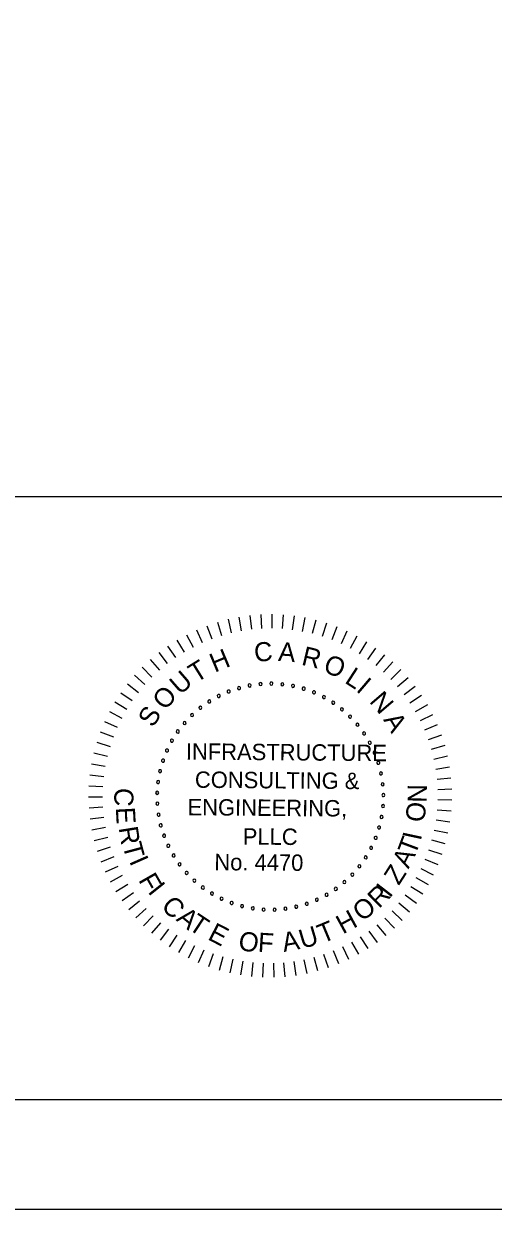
# Model space of a CAD drawing. Extents: x 1970675.2 to 1970711.3, y 796145.2 to 796167.2.
# Drawn here: x 1970700.45 to 1970702.59, y 796145.25 to 796150.65 of the extents above; entities that cross this region are included whole.
import ezdxf

# ---------------------------------------------------------------- set-up
doc = ezdxf.new("R2010")
doc.units = 0
for name, color, linetype in [('BR_BORDER LINES', 7, 'Continuous'), ('BR_TEXT', 7, 'Continuous'), ('Level 31', 7, 'Continuous')]:
    doc.layers.add(name, color=color, linetype=linetype)

msp = doc.modelspace()

# ---------------------------------------------------------------- linework, layer by layer
at = {"layer": 'BR_BORDER LINES'}
for p, q in [((1970697.8703, 796148.4964), (1970703.2355, 796148.4964)), ((1970677.0698, 796145.7463), (1970710.7358, 796145.7463))]:
    msp.add_line(p, q, dxfattribs=at)
at = {"layer": 'BR_TEXT'}
for p, q in [((1970701.4761, 796147.9545), (1970701.4834, 796147.8913)), ((1970701.5265, 796147.9587), (1970701.5298, 796147.8951)), ((1970701.5769, 796147.9597), (1970701.5764, 796147.8961)), ((1970701.6274, 796147.9577), (1970701.623, 796147.8942)), ((1970701.2802, 796147.9077), (1970701.3025, 796147.8481)), ((1970701.328, 796147.9239), (1970701.3466, 796147.863)), ((1970701.3767, 796147.9371), (1970701.3916, 796147.8752)), ((1970701.4262, 796147.9473), (1970701.4372, 796147.8846)), ((1970701.6776, 796147.9526), (1970701.6693, 796147.8895)), ((1970701.7274, 796147.9445), (1970701.7153, 796147.882)), ((1970701.7767, 796147.9333), (1970701.7608, 796147.8717)), ((1970701.8251, 796147.9192), (1970701.8055, 796147.8586)), ((1970701.8726, 796147.9021), (1970701.8494, 796147.8428)), ((1970701.1879, 796147.8668), (1970701.2173, 796147.8103)), ((1970701.2334, 796147.8887), (1970701.2593, 796147.8305)), ((1970701.919, 796147.8822), (1970701.8922, 796147.8244)), ((1970701.9641, 796147.8594), (1970701.9338, 796147.8034)), ((1970701.1014, 796147.8149), (1970701.1374, 796147.7625)), ((1970701.1439, 796147.8422), (1970701.1766, 796147.7876)), ((1970702.0077, 796147.834), (1970701.974, 796147.78)), ((1970702.0497, 796147.8059), (1970702.0128, 796147.7541)), ((1970701.0217, 796147.7529), (1970701.0639, 796147.7052)), ((1970701.0606, 796147.7852), (1970701.0998, 796147.735)), ((1970702.0899, 796147.7754), (1970702.0499, 796147.7259)), ((1970702.1281, 796147.7424), (1970702.0852, 796147.6954)), ((1970700.9849, 796147.7184), (1970701.0299, 796147.6734)), ((1970702.1643, 796147.7072), (1970702.1186, 796147.6629)), ((1970700.9179, 796147.643), (1970700.968, 796147.6037)), ((1970700.9502, 796147.6817), (1970700.9979, 796147.6395)), ((1970702.1982, 796147.6699), (1970702.1499, 796147.6284)), ((1970702.2299, 796147.6305), (1970702.1791, 796147.5921)), ((1970700.8879, 796147.6023), (1970700.9404, 796147.5662)), ((1970702.259, 796147.5893), (1970702.206, 796147.5541)), ((1970700.8605, 796147.5599), (1970700.9151, 796147.5271)), ((1970702.2856, 796147.5464), (1970702.2305, 796147.5145)), ((1970700.8137, 796147.4705), (1970700.8719, 796147.4445)), ((1970700.8358, 796147.5159), (1970700.8922, 796147.4865)), ((1970702.3095, 796147.5019), (1970702.2526, 796147.4734)), ((1970700.7945, 796147.4238), (1970700.8541, 796147.4014)), ((1970702.3307, 796147.4561), (1970702.2722, 796147.4311)), ((1970700.7782, 796147.3761), (1970700.839, 796147.3574)), ((1970702.3491, 796147.4091), (1970702.2891, 796147.3877)), ((1970702.3645, 796147.361), (1970702.3033, 796147.3433)), ((1970700.7648, 796147.3274), (1970700.8267, 796147.3124)), ((1970702.377, 796147.3121), (1970702.3148, 796147.2982)), ((1970700.7543, 796147.278), (1970700.817, 796147.2668)), ((1970702.3864, 796147.2625), (1970702.3236, 796147.2524)), ((1970700.747, 796147.228), (1970700.8102, 796147.2207)), ((1970702.3929, 796147.2124), (1970702.3295, 796147.2062)), ((1970700.7426, 796147.1777), (1970700.8062, 796147.1743)), ((1970702.3963, 796147.1621), (1970702.3326, 796147.1597)), ((1970700.7414, 796147.1273), (1970700.8051, 796147.1277)), ((1970702.3965, 796147.1116), (1970702.3329, 796147.1131)), ((1970700.7432, 796147.0768), (1970700.8067, 796147.0812)), ((1970702.3938, 796147.0612), (1970702.3303, 796147.0666)), ((1970700.7481, 796147.0266), (1970700.8113, 796147.0348)), ((1970700.7561, 796146.9767), (1970700.8186, 796146.9888)), ((1970702.3879, 796147.011), (1970702.3249, 796147.0203)), ((1970700.7671, 796146.9275), (1970700.8287, 796146.9433)), ((1970702.3671, 796146.9123), (1970702.3057, 796146.9291)), ((1970702.379, 796146.9613), (1970702.3167, 796146.9744)), ((1970700.781, 796146.8789), (1970700.8416, 796146.8985)), ((1970702.3522, 796146.864), (1970702.2919, 796146.8846)), ((1970700.7979, 796146.8314), (1970700.8572, 796146.8546)), ((1970702.3344, 796146.8168), (1970702.2755, 796146.841)), ((1970700.8177, 796146.7849), (1970700.8755, 796146.8117)), ((1970700.8403, 796146.7397), (1970700.8963, 796146.77)), ((1970702.3138, 796146.7707), (1970702.2564, 796146.7985)), ((1970700.8655, 796146.696), (1970700.9196, 796146.7297)), ((1970702.2643, 796146.6828), (1970702.2107, 796146.7173)), ((1970702.2904, 796146.726), (1970702.2348, 796146.7572)), ((1970700.8934, 796146.654), (1970700.9453, 796146.6908)), ((1970702.2356, 796146.6412), (1970702.1843, 796146.6789)), ((1970700.9238, 796146.6137), (1970700.9734, 796146.6536)), ((1970700.9566, 796146.5753), (1970701.0037, 796146.6182)), ((1970702.1709, 796146.5638), (1970702.1245, 796146.6074)), ((1970702.2044, 796146.6015), (1970702.1555, 796146.6423)), ((1970700.9917, 796146.539), (1970701.0361, 796146.5847)), ((1970701.0289, 796146.5049), (1970701.0704, 796146.5532)), ((1970702.1351, 796146.5281), (1970702.0915, 796146.5745)), ((1970701.0682, 796146.4731), (1970701.1066, 796146.5239)), ((1970701.1093, 796146.4438), (1970701.1446, 796146.4968)), ((1970702.0574, 796146.4637), (1970702.0198, 796146.5151)), ((1970702.0973, 796146.4948), (1970702.0566, 796146.5437)), ((1970701.1521, 796146.4171), (1970701.1841, 796146.4721)), ((1970701.1965, 796146.393), (1970701.225, 796146.4499)), ((1970701.9276, 796146.386), (1970701.9, 796146.4434)), ((1970701.9725, 796146.4093), (1970701.9414, 796146.4648)), ((1970702.0158, 796146.4352), (1970701.9813, 796146.4888)), ((1970701.2422, 796146.3716), (1970701.2673, 796146.4302)), ((1970701.2892, 796146.3531), (1970701.3106, 796146.4131)), ((1970701.3372, 796146.3375), (1970701.3549, 796146.3986)), ((1970701.386, 796146.3248), (1970701.4001, 796146.3869)), ((1970701.7859, 796146.3332), (1970701.7691, 796146.3947)), ((1970701.8342, 796146.3479), (1970701.8137, 796146.4082)), ((1970701.8815, 796146.3656), (1970701.8574, 796146.4245)), ((1970701.4356, 796146.3152), (1970701.4458, 796146.378)), ((1970701.4856, 796146.3086), (1970701.492, 796146.3719)), ((1970701.536, 796146.305), (1970701.5385, 796146.3686)), ((1970701.5865, 796146.3045), (1970701.5851, 796146.3682)), ((1970701.6369, 796146.3071), (1970701.6316, 796146.3706)), ((1970701.6871, 796146.3128), (1970701.6779, 796146.3758)), ((1970701.7368, 796146.3215), (1970701.7238, 796146.3838))]:
    msp.add_line(p, q, dxfattribs=at)
for centre, start, end in [((1970701.4268, 796147.6235), 16.1422, 196.1422), ((1970701.4753, 796147.635), 10.6038, 190.6038), ((1970701.4753, 796147.635), 190.6038, 10.6038), ((1970701.5247, 796147.6417), 5.0653, 185.0653), ((1970701.5247, 796147.6417), 185.0653, 5.0653), ((1970701.5745, 796147.6436), 359.5268, 179.5268), ((1970701.5745, 796147.6436), 179.5268, 359.5268), ((1970701.6242, 796147.6407), 173.9884, 353.9884), ((1970701.6242, 796147.6407), 353.9884, 173.9884), ((1970701.6735, 796147.6329), 168.4499, 348.4499), ((1970701.6735, 796147.6329), 348.4499, 168.4499), ((1970701.3343, 796147.587), 27.2191, 207.2191), ((1970701.3343, 796147.587), 207.2191, 27.2191), ((1970701.3797, 796147.6075), 21.6807, 201.6807), ((1970701.3797, 796147.6075), 201.6807, 21.6807), ((1970701.4268, 796147.6235), 196.1422, 16.1422), ((1970701.7217, 796147.6205), 162.9114, 342.9114), ((1970701.7217, 796147.6205), 342.9114, 162.9114), ((1970701.7686, 796147.6035), 157.373, 337.373), ((1970701.7686, 796147.6035), 337.373, 157.373), ((1970701.8135, 796147.582), 151.8345, 331.8345), ((1970701.8135, 796147.582), 331.8345, 151.8345), ((1970701.2504, 796147.5333), 38.2961, 218.2961), ((1970701.2504, 796147.5333), 218.2961, 38.2961), ((1970701.291, 796147.5621), 32.7576, 212.7576), ((1970701.291, 796147.5621), 212.7576, 32.7576), ((1970701.8562, 796147.5563), 146.2961, 326.2961), ((1970701.8562, 796147.5563), 326.2961, 146.2961), ((1970701.8962, 796147.5266), 140.7576, 320.7576), ((1970701.8962, 796147.5266), 320.7576, 140.7576), ((1970701.1785, 796147.4645), 49.373, 229.373), ((1970701.1785, 796147.4645), 229.373, 49.373), ((1970701.2128, 796147.5006), 43.8345, 223.8345), ((1970701.2128, 796147.5006), 223.8345, 43.8345), ((1970701.9332, 796147.4932), 135.2191, 315.2191), ((1970701.9332, 796147.4932), 315.2191, 135.2191), ((1970701.1478, 796147.4252), 54.9114, 234.9114), ((1970701.1478, 796147.4252), 234.9114, 54.9114), ((1970701.9668, 796147.4564), 129.6807, 309.6807), ((1970701.9668, 796147.4564), 309.6807, 129.6807), ((1970701.9966, 796147.4165), 124.1422, 304.1422), ((1970701.9966, 796147.4165), 304.1422, 124.1422), ((1970701.1211, 796147.3831), 60.4499, 240.4499), ((1970701.1211, 796147.3831), 240.4499, 60.4499), ((1970702.0225, 796147.3739), 118.6038, 298.6038), ((1970702.0225, 796147.3739), 298.6038, 118.6038), ((1970701.0986, 796147.3387), 65.9884, 245.9884), ((1970701.0986, 796147.3387), 245.9884, 65.9884), ((1970702.0441, 796147.329), 113.0653, 293.0653), ((1970702.0441, 796147.329), 293.0653, 113.0653), ((1970701.0804, 796147.2923), 71.5268, 251.5268), ((1970701.0804, 796147.2923), 251.5268, 71.5268), ((1970702.0613, 796147.2822), 107.5268, 287.5268), ((1970702.0613, 796147.2822), 287.5268, 107.5268), ((1970701.0579, 796147.1953), 82.6038, 262.6038), ((1970701.0579, 796147.1953), 262.6038, 82.6038), ((1970701.0668, 796147.2443), 77.0653, 257.0653), ((1970701.0668, 796147.2443), 257.0653, 77.0653), ((1970702.0739, 796147.234), 101.9884, 281.9884), ((1970702.0739, 796147.234), 281.9884, 101.9884), ((1970701.0538, 796147.1456), 88.1422, 268.1422), ((1970701.0538, 796147.1456), 268.1422, 88.1422), ((1970702.0818, 796147.1848), 96.4499, 276.4499), ((1970702.0818, 796147.1848), 276.4499, 96.4499), ((1970701.0545, 796147.0958), 93.6807, 273.6807), ((1970701.0545, 796147.0958), 273.6807, 93.6807), ((1970702.0832, 796147.0853), 85.373, 265.373), ((1970702.0849, 796147.1351), 90.9114, 270.9114), ((1970702.0832, 796147.0853), 265.373, 85.373), ((1970702.0849, 796147.1351), 270.9114, 90.9114), ((1970701.06, 796147.0463), 99.2191, 279.2191), ((1970701.06, 796147.0463), 279.2191, 99.2191), ((1970702.0766, 796147.0359), 79.8345, 259.8345), ((1970702.0766, 796147.0359), 259.8345, 79.8345), ((1970701.0703, 796146.9975), 104.7576, 284.7576), ((1970701.0703, 796146.9975), 284.7576, 104.7576), ((1970702.0654, 796146.9873), 74.2961, 254.2961), ((1970702.0654, 796146.9873), 254.2961, 74.2961), ((1970701.0852, 796146.95), 110.2961, 290.2961), ((1970701.0852, 796146.95), 290.2961, 110.2961), ((1970702.0495, 796146.9401), 68.7576, 248.7576), ((1970702.0495, 796146.9401), 248.7576, 68.7576), ((1970701.1046, 796146.9041), 115.8345, 295.8345), ((1970701.1046, 796146.9041), 295.8345, 115.8345), ((1970702.0291, 796146.8946), 63.2191, 243.2191), ((1970702.0291, 796146.8946), 243.2191, 63.2191), ((1970701.1284, 796146.8603), 121.373, 301.373), ((1970701.1284, 796146.8603), 301.373, 121.373), ((1970701.1563, 796146.819), 126.9114, 306.9114), ((1970701.1563, 796146.819), 306.9114, 126.9114), ((1970702.0045, 796146.8513), 57.6807, 237.6807), ((1970702.0045, 796146.8513), 237.6807, 57.6807), ((1970701.188, 796146.7806), 132.4499, 312.4499), ((1970701.188, 796146.7806), 312.4499, 132.4499), ((1970701.9432, 796146.7728), 46.6038, 226.6038), ((1970701.9432, 796146.7728), 226.6038, 46.6038), ((1970701.9758, 796146.8106), 52.1422, 232.1422), ((1970701.9758, 796146.8106), 232.1422, 52.1422), ((1970701.2233, 796146.7454), 137.9884, 317.9884), ((1970701.2233, 796146.7454), 317.9884, 137.9884), ((1970701.2618, 796146.7138), 143.5268, 323.5268), ((1970701.2618, 796146.7138), 323.5268, 143.5268), ((1970701.8681, 796146.7076), 35.5268, 215.5268), ((1970701.8681, 796146.7076), 215.5268, 35.5268), ((1970701.9072, 796146.7384), 41.0653, 221.0653), ((1970701.9072, 796146.7384), 221.0653, 41.0653), ((1970701.3032, 796146.6861), 149.0653, 329.0653), ((1970701.3032, 796146.6861), 329.0653, 149.0653), ((1970701.3471, 796146.6625), 154.6038, 334.6038), ((1970701.3471, 796146.6625), 334.6038, 154.6038), ((1970701.7817, 796146.658), 24.4499, 204.4499), ((1970701.7817, 796146.658), 204.4499, 24.4499), ((1970701.8261, 796146.6807), 29.9884, 209.9884), ((1970701.8261, 796146.6807), 209.9884, 29.9884), ((1970701.3931, 796146.6432), 160.1422, 340.1422), ((1970701.3931, 796146.6432), 340.1422, 160.1422), ((1970701.4407, 796146.6285), 165.6807, 345.6807), ((1970701.4407, 796146.6285), 345.6807, 165.6807), ((1970701.4895, 796146.6184), 171.2191, 351.2191), ((1970701.4895, 796146.6184), 351.2191, 171.2191), ((1970701.539, 796146.6131), 356.7576, 176.7576), ((1970701.539, 796146.6131), 176.7576, 356.7576), ((1970701.5889, 796146.6126), 2.2961, 182.2961), ((1970701.5889, 796146.6126), 182.2961, 2.2961), ((1970701.6385, 796146.6169), 7.8345, 187.8345), ((1970701.6385, 796146.6169), 187.8345, 7.8345), ((1970701.6875, 796146.6259), 13.373, 193.373), ((1970701.6875, 796146.6259), 193.373, 13.373), ((1970701.7354, 796146.6397), 18.9114, 198.9114), ((1970701.7354, 796146.6397), 198.9114, 18.9114)]:
    msp.add_arc(centre, 0.00701, start, end, dxfattribs=at)
at = {"layer": 'Level 31'}
msp.add_lwpolyline([(1970675.2365, 796145.2464), (1970711.2364, 796145.2464), (1970711.2364, 796167.2463), (1970675.2365, 796167.2463)], close=True, dxfattribs=at)

# ---------------------------------------------------------------- texts
at = {"layer": 'BR_TEXT'}
for s, height, rotation, p in [('H', 0.0872, 22.7882, (1970701.3162, 796147.6927)), ('C', 0.0872, 4.7281, (1970701.499, 796147.7421)), ('A', 0.0872, 355.6981, (1970701.6035, 796147.7471)), ('R', 0.0872, 346.6681, (1970701.7077, 796147.7301)), ('T', 0.0872, 31.8182, (1970701.2313, 796147.6451)), ('O', 0.0872, 337.638, (1970701.8055, 796147.7003)), ('U', 0.0872, 40.8482, (1970701.158, 796147.589)), ('L', 0.0872, 327.108, (1970701.9043, 796147.6498)), ('I', 0.0872, 319.578, (1970701.9569, 796147.612)), ('O', 0.0872, 49.8782, (1970701.091, 796147.518)), ('N', 0.0872, 310.548, (1970702.0177, 796147.5612)), ('S', 0.0872, 58.9083, (1970701.0356, 796147.4398)), ('A', 0.0872, 301.5179, (1970702.0828, 796147.4788)), ('INFRASTRUCTURE', 0.074771, 359.5268, (1970701.1842, 796147.2972)), ('CONSULTING &', 0.074771, 359.5268, (1970701.2255, 796147.1686)), ('C', 0.0872, 267.025, (1970700.8606, 796147.1698)), ('N', 0.0872, 89.2085, (1970702.2821, 796147.1001)), ('ENGINEERING,', 0.074771, 359.5268, (1970701.1919, 796147.0432)), ('O', 0.0872, 83.2085, (1970702.271, 796147.0086)), ('E', 0.0872, 273.025, (1970700.865, 796147.0783)), ('R', 0.0872, 279.025, (1970700.8778, 796146.986)), ('PLLC', 0.07477, 359.5268, (1970701.4436, 796146.9096)), ('T', 0.0872, 285.025, (1970700.8952, 796146.9072)), ('T', 0.0872, 69.3954, (1970702.2298, 796146.8568)), ('I', 0.0872, 77.9093, (1970702.2555, 796146.9243)), ('A', 0.0872, 63.3954, (1970702.199, 796146.7965)), ('I', 0.0872, 293.7713, (1970700.9249, 796146.8341)), ('No. 4470', 0.07477, 359.5268, (1970701.3141, 796146.7927)), ('Z', 0.0872, 57.3954, (1970702.1551, 796146.7202)), ('F', 0.0872, 299.7713, (1970700.9661, 796146.748)), ('I', 0.0872, 308.5268, (1970701.0082, 796146.6942)), ('R', 0.0872, 44.5268, (1970702.0647, 796146.6152)), ('I', 0.0872, 52.3339, (1970702.1141, 796146.6625)), ('C', 0.0872, 314.5268, (1970701.0675, 796146.6241)), ('O', 0.0872, 38.5268, (1970701.9881, 796146.5552)), ('A', 0.0872, 320.5268, (1970701.1367, 796146.5655)), ('H', 0.0872, 28.5268, (1970701.9, 796146.4992)), ('T', 0.0872, 326.5268, (1970701.1911, 796146.527)), ('E', 0.0872, 332.5268, (1970701.2797, 796146.4792)), ('T', 0.0872, 22.5268, (1970701.8068, 796146.4575)), ('O', 0.0872, 350.5268, (1970701.4198, 796146.4304)), ('F', 0.0872, 356.5268, (1970701.5113, 796146.4212)), ('A', 0.0872, 10.5268, (1970701.6312, 796146.4196)), ('U', 0.0872, 16.5268, (1970701.7151, 796146.4331))]:
    msp.add_text(s, height=height, rotation=rotation, dxfattribs=at).set_placement(p)

doc.saveas('drawing.dxf')
